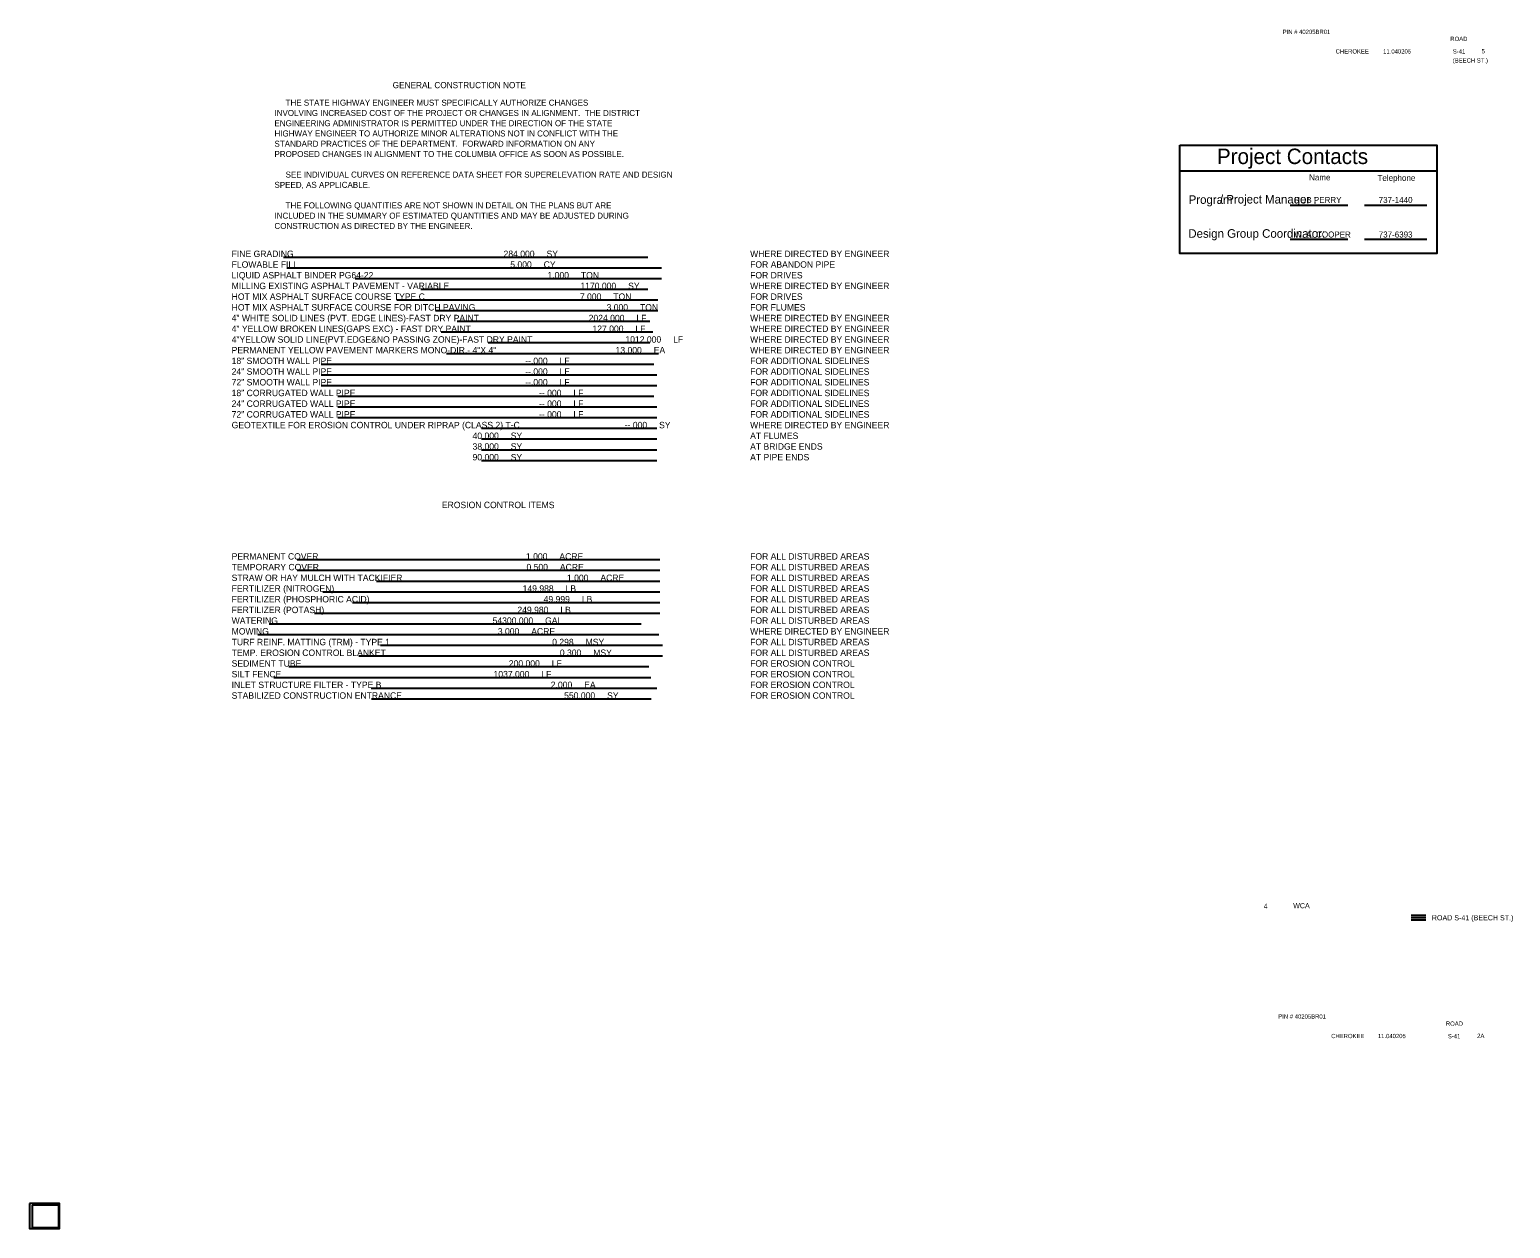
# Model space of a CAD drawing. Extents: x 160093 to 164626, y 177093 to 182727.
# Drawn here: x 162874 to 164604, y 181327 to 182727 of the extents above; entities that cross this region are included whole.
import ezdxf

# ---------------------------------------------------------------- set-up
doc = ezdxf.new("R2010")
doc.units = 0
for name, color, linetype in [('Default', 7, 'Continuous'), ('Level 37', 7, 'Continuous'), ('Level 39', 7, 'Continuous'), ('Level 49', 7, 'Continuous'), ('Level 50', 7, 'Continuous')]:
    doc.layers.add(name, color=color, linetype=linetype)

msp = doc.modelspace()

# ---------------------------------------------------------------- linework, layer by layer
at = {"layer": 'Default'}
for p, q in [((163170.8, 182461.5), (163596.5, 182461.5)), ((163174.7, 182449), (163612.5, 182449)), ((163348.5, 182399), (163608.3, 182399)), ((163373.8, 182386.5), (163598.8, 182386.5)), ((163355.3, 182374), (163602.3, 182374)), ((163361.3, 182349), (163608.9, 182349)), ((163410.1, 182361.5), (163598.8, 182361.5)), ((163214.9, 182336.5), (163603.5, 182336.5)), ((163214.9, 182324), (163607.1, 182324)), ((163214.9, 182311.5), (163607.1, 182311.5)), ((163234.5, 182299), (163603.5, 182299)), ((163234.5, 182286.5), (163607.1, 182286.5)), ((163234.5, 182274), (163607.1, 182274)), ((163402.1, 182261.5), (163607.1, 182261.5)), ((163402.1, 182249), (163607.1, 182249)), ((163402.1, 182236.5), (163607.1, 182236.5)), ((163402.1, 182224), (163607.1, 182224)), ((163186.9, 182108.1), (163610.7, 182108.1)), ((163186.9, 182095.6), (163610.7, 182095.6)), ((163216.9, 182070.6), (163610.7, 182070.6)), ((163279.8, 182083.1), (163610.7, 182083.1)), ((163251.5, 182058.1), (163610.7, 182058.1)), ((163207, 182045.6), (163610.7, 182045.6)), ((163141.1, 182020.6), (163609.5, 182020.6)), ((163154.2, 182033.1), (163588.7, 182033.1)), ((163284.2, 182008.1), (163613.7, 182008.1)), ((163177, 181983.1), (163597.9, 181983.1)), ((163259.1, 181995.6), (163613.7, 181995.6)), ((163159.5, 181970.6), (163600, 181970.6)), ((163273.3, 181958.1), (163607.1, 181958.1)), ((163273.6, 181945.6), (163600.4, 181945.6)), ((164488.3, 181692.9), (164505.6, 181692.9)), ((164488.3, 181690.1), (164505.6, 181690.1)), ((164488.3, 181687.2), (164505.6, 181687.2))]:
    msp.add_line(p, q, dxfattribs=at)
for points in [[(162874.4, 181356.2), (162874.4, 181327), (162909.1, 181327), (162909.1, 181356.2)], [(162877.2, 181354.1), (162877.2, 181327.9), (162908.4, 181327.9), (162908.4, 181354.1)]]:
    msp.add_lwpolyline(points, close=True, dxfattribs=at)
at = {"layer": 'Level 37'}
for p, q in [((163254.8, 182436.5), (163612.5, 182436.5)), ((163331.5, 182424), (163596.5, 182424)), ((163303.4, 182411.5), (163608.3, 182411.5))]:
    msp.add_line(p, q, dxfattribs=at)
at = {"layer": 'Level 39'}
for p, q in [((164218, 182562.2), (164518.2, 182562.2)), ((164346.9, 182522.2), (164414.3, 182522.2)), ((164433.7, 182522.2), (164506.8, 182522.2)), ((164346.9, 182482.2), (164414.3, 182482.2)), ((164433.7, 182482.2), (164506.8, 182482.2))]:
    msp.add_line(p, q, dxfattribs=at)
msp.add_lwpolyline([(164218, 182592.2), (164518.2, 182592.2), (164518.2, 182465.6), (164218, 182465.6)], close=True, dxfattribs=at)

# ---------------------------------------------------------------- texts
at = {"layer": 'Default'}
for s, height, p in [('PIN # 40205BR01', 5, (164338.2, 182722)), ('ROAD', 5, (164534.1, 182713.8)), ('11.040205', 5, (164455.6, 182699.2)), ('S-41', 5, (164537, 182699.1)), ('(BEECH ST.)', 5, (164537, 182688.6)), ('FINE GRADING                                                                                        284.000     SY', 7.5, (163110.4, 182461.5)), ('WHERE DIRECTED BY ENGINEER', 7.5, (163716.1, 182461.5)), ('FLOWABLE FILL                                                                                         5.000     CY', 7.5, (163110.4, 182449)), ('FOR ABANDON PIPE', 7.5, (163716.1, 182449)), ('LIQUID ASPHALT BINDER PG64-22                                                                         1.000     TON', 7.5, (163110.4, 182436.5)), ('MILLING EXISTING ASPHALT PAVEMENT - VARIABLE                                                       1170.000     SY', 7.5, (163110.4, 182424)), ('HOT MIX ASPHALT SURFACE COURSE TYPE C                                                                 7.000     TON', 7.5, (163110.4, 182411.5)), ('HOT MIX ASPHALT SURFACE COURSE FOR DITCH PAVING                                                       3.000     TON', 7.5, (163110.4, 182399)), ('FOR FLUMES', 7.5, (163716.1, 182399)), ('4" WHITE SOLID LINES (PVT. EDGE LINES)-FAST DRY PAINT                                              2024.000     LF', 7.5, (163110.4, 182386.5)), ('4" YELLOW BROKEN LINES(GAPS EXC) - FAST DRY PAINT                                                   127.000     LF', 7.5, (163110.4, 182374)), ('WHERE DIRECTED BY ENGINEER', 7.5, (163716.1, 182386.5)), ('WHERE DIRECTED BY ENGINEER', 7.5, (163716.1, 182374)), ('4"YELLOW SOLID LINE(PVT.EDGE&NO PASSING ZONE)-FAST DRY PAINT                                       1012.000     LF', 7.5, (163110.4, 182361.5)), ('WHERE DIRECTED BY ENGINEER', 7.5, (163716.1, 182361.5)), ('PERMANENT YELLOW PAVEMENT MARKERS MONO-DIR.- 4"X 4"                                                  13.000     EA', 7.5, (163110.4, 182349)), ('WHERE DIRECTED BY ENGINEER', 7.5, (163716.1, 182349)), ('24" SMOOTH WALL PIPE                                                                                 --.000     LF', 7.5, (163110.4, 182324)), ('18" SMOOTH WALL PIPE                                                                                 --.000     LF', 7.5, (163110.4, 182336.5)), ('FOR ADDITIONAL SIDELINES', 7.5, (163716.1, 182336.5)), ('FOR ADDITIONAL SIDELINES', 7.5, (163716.1, 182324)), ('72" SMOOTH WALL PIPE                                                                                 --.000     LF', 7.5, (163110.4, 182311.5)), ('FOR ADDITIONAL SIDELINES', 7.5, (163716.1, 182311.5)), ('24" CORRUGATED WALL PIPE                                                                             --.000     LF', 7.5, (163110.4, 182286.5)), ('18" CORRUGATED WALL PIPE                                                                             --.000     LF', 7.5, (163110.4, 182299)), ('FOR ADDITIONAL SIDELINES', 7.5, (163716.1, 182299)), ('FOR ADDITIONAL SIDELINES', 7.5, (163716.1, 182286.5)), ('72" CORRUGATED WALL PIPE                                                                             --.000     LF', 7.5, (163110.4, 182274)), ('FOR ADDITIONAL SIDELINES', 7.5, (163716.1, 182274)), ('GEOTEXTILE FOR EROSION CONTROL UNDER RIPRAP (CLASS 2) T-C                                            --.000     SY', 7.5, (163110.4, 182261.5)), ('WHERE DIRECTED BY ENGINEER', 7.5, (163716.1, 182261.5)), ('                                                                                                     40.000     SY', 7.5, (163110.4, 182249)), ('                                                                                                     38.000     SY', 7.5, (163110.4, 182236.5)), ('AT FLUMES', 7.5, (163716.1, 182249)), ('AT BRIDGE ENDS', 7.5, (163716.1, 182236.5)), ('                                                                                                     90.000     SY', 7.5, (163110.4, 182224)), ('AT PIPE ENDS', 7.5, (163716.1, 182224)), ('EROSION CONTROL ITEMS', 7.5, (163356, 182168.2)), ('PERMANENT COVER                                                                                       1.000     ACRE', 7.5, (163110.4, 182108.1)), ('FOR ALL DISTURBED AREAS', 7.5, (163716.1, 182108.1)), ('TEMPORARY COVER                                                                                       0.500     ACRE', 7.5, (163110.4, 182095.6)), ('STRAW OR HAY MULCH WITH TACKIFIER                                                                     1.000     ACRE', 7.5, (163110.4, 182083.1)), ('FOR ALL DISTURBED AREAS', 7.5, (163716.1, 182095.6)), ('FOR ALL DISTURBED AREAS', 7.5, (163716.1, 182083.1)), ('FERTILIZER (NITROGEN)                                                                               149.988     LB', 7.5, (163110.4, 182070.6)), ('FOR ALL DISTURBED AREAS', 7.5, (163716.1, 182070.6)), ('FERTILIZER (PHOSPHORIC ACID)                                                                         49.999     LB', 7.5, (163110.4, 182058.1)), ('FERTILIZER (POTASH)                                                                                 249.980     LB', 7.5, (163110.4, 182045.6)), ('FOR ALL DISTURBED AREAS', 7.5, (163716.1, 182058.1)), ('FOR ALL DISTURBED AREAS', 7.5, (163716.1, 182045.6)), ('WATERING                                                                                          54300.000     GAL', 7.5, (163110.4, 182033.1)), ('FOR ALL DISTURBED AREAS', 7.5, (163716.1, 182033.1)), ('MOWING                                                                                                3.000     ACRE', 7.5, (163110.4, 182020.6)), ('WHERE DIRECTED BY ENGINEER', 7.5, (163716.1, 182020.6)), ('TURF REINF. MATTING (TRM) - TYPE 1                                                                    0.298     MSY', 7.5, (163110.4, 182008.1)), ('TEMP. EROSION CONTROL BLANKET                                                                         0.300     MSY', 7.5, (163110.4, 181995.6)), ('FOR ALL DISTURBED AREAS', 7.5, (163716.1, 182008.1)), ('FOR ALL DISTURBED AREAS', 7.5, (163716.1, 181995.6)), ('SEDIMENT TUBE                                                                                       200.000     LF', 7.5, (163110.4, 181983.1)), ('FOR EROSION CONTROL', 7.5, (163716.1, 181983.1)), ('SILT FENCE                                                                                         1037.000     LF', 7.5, (163110.4, 181970.6)), ('INLET STRUCTURE FILTER - TYPE B                                                                       2.000     EA ', 7.5, (163110.4, 181958.1)), ('FOR EROSION CONTROL', 7.5, (163716.1, 181970.6)), ('FOR EROSION CONTROL', 7.5, (163716.1, 181958.1)), ('STABILIZED CONSTRUCTION ENTRANCE                                                                    550.000     SY', 7.5, (163110.4, 181945.6)), ('FOR EROSION CONTROL', 7.5, (163716.1, 181945.6)), ('ROAD S-41 (BEECH ST.)', 6, (164512.5, 181686.8)), ('ROAD', 5, (164528.9, 181563.7)), ('11.040205', 5, (164449.4, 181549.2)), ('S-41', 5, (164531.2, 181549))]:
    msp.add_text(s, height=height, dxfattribs=at).set_placement(p)
at = {"layer": 'Level 37'}
for s, height, p in [('CHEROKEE', 5, (164400.1, 182699.2)), ('5', 5, (164570.6, 182699.4)), ('ROB PERRY', 7, (164351.8, 182524.7)), ('737-1440', 7, (164450.4, 182524.7)), ('W. A. COOPER', 7, (164351.8, 182484.3)), ('737-6393', 7, (164450.4, 182484.3)), ('FOR DRIVES', 7.5, (163716.1, 182436.5)), ('WHERE DIRECTED BY ENGINEER', 7.5, (163716.1, 182424)), ('FOR DRIVES', 7.5, (163716.1, 182411.5)), ('PIN # 40205BR01', 5, (164333.1, 181572)), ('CHEROKEE', 5, (164394.9, 181549.2)), ('2A', 5, (164565.4, 181549.4))]:
    msp.add_text(s, height=height, dxfattribs=at).set_placement(p)
at = {"layer": 'Level 39'}
for s, height, p in [('Project Contacts', 18, (164261.4, 182570.1)), ('Name', 7, (164369.1, 182551)), ('Telephone', 7, (164449, 182550.4)), ('Program', 10, (164228.4, 182523.6)), ('/ Project Manager :', 10, (164264.9, 182524)), ('Design Group Coordinator:', 10, (164228, 182484))]:
    msp.add_text(s, height=height, dxfattribs=at).set_placement(p)
at = {"layer": 'Level 49'}
for s, height, p in [('GENERAL CONSTRUCTION NOTE', 7.2, (163298.5, 182658.7)), ('     THE STATE HIGHWAY ENGINEER MUST SPECIFICALLY AUTHORIZE CHANGES', 7, (163160.4, 182638.3)), ('INVOLVING INCREASED COST OF THE PROJECT OR CHANGES IN ALIGNMENT.  THE DISTRICT', 7, (163160.4, 182626.3)), ('ENGINEERING ADMINISTRATOR IS PERMITTED UNDER THE DIRECTION OF THE STATE', 7, (163160.4, 182614.3)), ('HIGHWAY ENGINEER TO AUTHORIZE MINOR ALTERATIONS NOT IN CONFLICT WITH THE ', 7, (163160.4, 182602.3)), ('STANDARD PRACTICES OF THE DEPARTMENT.  FORWARD INFORMATION ON ANY ', 7, (163160.4, 182590.3)), ('PROPOSED CHANGES IN ALIGNMENT TO THE COLUMBIA OFFICE AS SOON AS POSSIBLE.', 7, (163160.4, 182578.3)), ('     SEE INDIVIDUAL CURVES ON REFERENCE DATA SHEET FOR SUPERELEVATION RATE AND DESIGN', 7, (163160.4, 182554.3)), ('SPEED, AS APPLICABLE.', 7, (163160.4, 182542.3)), ('     THE FOLLOWING QUANTITIES ARE NOT SHOWN IN DETAIL ON THE PLANS BUT ARE', 7, (163160.4, 182518.3)), ('CONSTRUCTION AS DIRECTED BY THE ENGINEER.', 7, (163160.4, 182494.3)), ('INCLUDED IN THE SUMMARY OF ESTIMATED QUANTITIES AND MAY BE ADJUSTED DURING', 7, (163160.4, 182506.3))]:
    msp.add_text(s, height=height, dxfattribs=at).set_placement(p)
at = {"layer": 'Level 50'}
for s, p in [('4', (164316.1, 181700.4)), ('WCA', (164350.5, 181700.9))]:
    msp.add_text(s, height=6, dxfattribs=at).set_placement(p)

doc.saveas('drawing.dxf')
